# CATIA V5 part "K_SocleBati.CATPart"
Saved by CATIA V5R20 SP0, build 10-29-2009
Part number: Socle_bati
Bounding box of the stored display mesh (mm): x 5 to 30, y -299.606 to 15, z -130 to 130
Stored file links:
  G:\Khaled_CFAO_2011\ST2M\ST2M_GR2\jcoetard\Khaled\CAD_CATIA\K_SocleBati.CATPart
  J:\Thinkmotion\Thinkmotion_COETARD\Maquette_catia\Maquette_catia_R20_Licence_education\jcharlescoetard.CATPRODUCT\Assemblage_Pince_Prehension_Mors_Paralleles.CATProduct
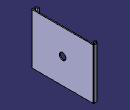
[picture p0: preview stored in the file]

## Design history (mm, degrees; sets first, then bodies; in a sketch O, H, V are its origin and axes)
Set1
  Plane1 "Plan_socle_bati": linked copy from another document
  Point1: linked copy from another document
  Point2: linked copy from another document
  Point3 "Point_centre_écrou": linked copy from another document
Body1 (main body)
  Sketch1 on Plane1, origin (30, 0, 0), H (0, 1, 0), V (0, 0, 1)
    line L1 (-299.606, 130) -> (15, 130)
    line L2 (15, 130) -> (15, -130)
    line L3 (15, -130) -> (-299.606, -130)
    line L4 (-299.606, -130) -> (-299.606, 130)
    reference projected point E1 (0, 150) from Point1
    reference projected point E2 (0, -150) from Point2
    construction line L5 (0, 90.2499) -> (0, -66.5362)
    point P5 (0, 90.2499)
    distance E1 L1 = 20
    distance L3 E2 = 20
    distance L5 L2 = 15
    length L1 = 314.606
    horizontal: L1 H, L3 H
    vertical: L2 V, L4 V, L5 V
    coincidence: P5 V
  Pad1: profile Sketch1, direction (-1, 0, 0), length 5
  Sketch2 on end face of Pad1, origin (25, 0, 0), H (0, -1, 0), V (0, 0, 1)
    line L1 (-15, 130) -> (-10, 130)
    line L2 (-10, 130) -> (-10, -130)
    line L3 (-10, -130) -> (-15, -130)
    line L4 (-15, -130) -> (-15, 130)
    reference projected line E1 (-24.098, 130) -> (217.1715, 130) from edge [end face of Pad1 | face of Pad1 from Sketch1.L1]
    reference projected line E2 (217.1715, -130) -> (-24.098, -130) from edge [end face of Pad1 | face of Pad1 from Sketch1.L3]
    reference projected line E3 (-15, -80) -> (-15, 80) from edge [end face of Pad1 | face of Pad1 from Sketch1.L2]
    distance L2 L4 = 5
    horizontal: L1 H, L3 H
    vertical: L2 V, L4 V
    coincidence: L1 E1, L3 E2, L4 E3
  Pad2: profile Sketch2, direction (-1, 0, 0), length 15
  Sketch3 on face of Pad2 from Sketch2.L2, origin (0, 10, 0), H (1, 0, 0), V (0, 0, 1)
    line L1 (10, 130) -> (15, 130)
    line L2 (15, 130) -> (15, -130)
    line L3 (15, -130) -> (10, -130)
    line L4 (10, -130) -> (10, 130)
    reference projected line E1 (10, -80) -> (10, 80) from edge [face of Pad2 from Sketch2.L2 | end face of Pad2]
    reference projected line E2 (35, -130) -> (20, -130) from edge [face of Pad2 from Sketch2.L2 | face of Pad2]
    reference projected line E3 (35, 130) -> (20, 130) from edge [face of Pad2 | face of Pad2 from Sketch2.L2]
    distance L4 L2 = 5
    horizontal: L1 H, L3 H
    vertical: L2 V, L4 V
    coincidence: L4 E1, E2 L3, E3 L1
  Pad3: profile Sketch3, direction (0, -1, 0), length 10
  Sketch4 on face of Pad3, origin (10, 0, 0), H (0, -1, 0), V (0, 0, 1)
    line L1 (-5, 130) -> (0, 130)
    line L2 (0, 130) -> (0, -130)
    line L3 (0, -130) -> (-5, -130)
    line L4 (-5, -130) -> (-5, 130)
    reference projected line E1 (-10, 130) -> (-15, 130) from edge [face of Pad3 | face of Pad3]
    reference projected line E2 (-15, -130) -> (-10, -130) from edge [face of Pad3 | face of Pad3]
    reference projected line E3 (0, 80) -> (0, -80) from edge [face of Pad3 | end face of Pad3]
    distance L4 L2 = 5
    horizontal: L1 H, L3 H
    vertical: L2 V, L4 V
    coincidence: L1 E1, L3 E2, E3 L2
  Pad4: profile Sketch4, direction (-1, 0, 0), length 5
  Sketch5 on start face of Pad1, origin (30, -92.303, 0), H (0, 1, 0), V (0, 0, 1)
    point P1 (-50, 0)
    reference projected point E1 (-50, 0) from Point3
    coincidence: E1 P1
  Hole1: placed by Sketch5, at (30, -142.303, 0) direction (-1, 0, 0), diameter 30, depth 10
  Sketch6 on end face of Pad1, origin (25, 0, 0), H (0, -1, 0), V (0, 0, 1)
    line L1 (294.606, 130) -> (299.606, 130)
    line L2 (299.606, 130) -> (299.606, -130)
    line L3 (299.606, -130) -> (294.606, -130)
    line L4 (294.606, -130) -> (294.606, 130)
    reference projected line E1 (299.606, 180) -> (299.606, -180) from edge [end face of Pad1 | face of Pad1 from Sketch1.L4]
    reference projected line E2 (-15, 130) -> (299.606, 130) from edge [end face of Pad1 | face of Pad4]
    reference projected line E3 (299.606, -130) -> (-15, -130) from edge [end face of Pad1 | face of Pad4]
    distance L2 L4 = 5
    horizontal: L1 H, L3 H
    vertical: L2 V, L4 V
    coincidence: L2 E1, L1 E2, L3 E3
  Pad5: profile Sketch6, direction (-1, 0, 0), length 15
  Sketch7 on face of Pad5 from Sketch6.L4, origin (0, -294.606, 0), H (-1, 0, 0), V (0, 0, 1)
    line L1 (-15, 130) -> (-10, 130)
    line L2 (-10, 130) -> (-10, -130)
    line L3 (-10, -130) -> (-15, -130)
    line L4 (-15, -130) -> (-15, 130)
    reference projected line E1 (-10, 180) -> (-10, -180) from edge [face of Pad5 from Sketch6.L4 | end face of Pad5]
    reference projected line E2 (-45, -130) -> (-30, -130) from edge [face of Pad5 | face of Pad5 from Sketch6.L4]
    reference projected line E3 (-45, 130) -> (-30, 130) from edge [face of Pad5 from Sketch6.L4 | face of Pad5]
    distance L2 L4 = 5
    horizontal: L1 H, L3 H
    vertical: L2 V, L4 V
    coincidence: L2 E1, L3 E2, L1 E3
  Pad6: profile Sketch7, direction (0, 1, 0), length 10
  Sketch8 on face of Pad6, origin (10, 0, 0), H (0, -1, 0), V (0, 0, 1)
    line L1 (284.606, 130) -> (289.606, 130)
    line L2 (289.606, 130) -> (289.606, -130)
    line L3 (289.606, -130) -> (284.606, -130)
    line L4 (284.606, -130) -> (284.606, 130)
    reference projected line E1 (299.606, 130) -> (294.606, 130) from edge [face of Pad6 | face of Pad6]
    reference projected line E2 (294.606, -130) -> (299.606, -130) from edge [face of Pad6 | face of Pad6]
    reference projected line E3 (284.606, -180) -> (284.606, 180) from edge [face of Pad6 | end face of Pad6]
    distance L4 L2 = 5
    horizontal: L1 H, L3 H
    vertical: L2 V, L4 V
    coincidence: L1 E1, L3 E2, L4 E3
  Pad7: profile Sketch8, direction (-1, 0, 0), length 5
  Fillet1: radius 2, on start face of Pad1; end face of Pad1; face of Pad2; face of Pad5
